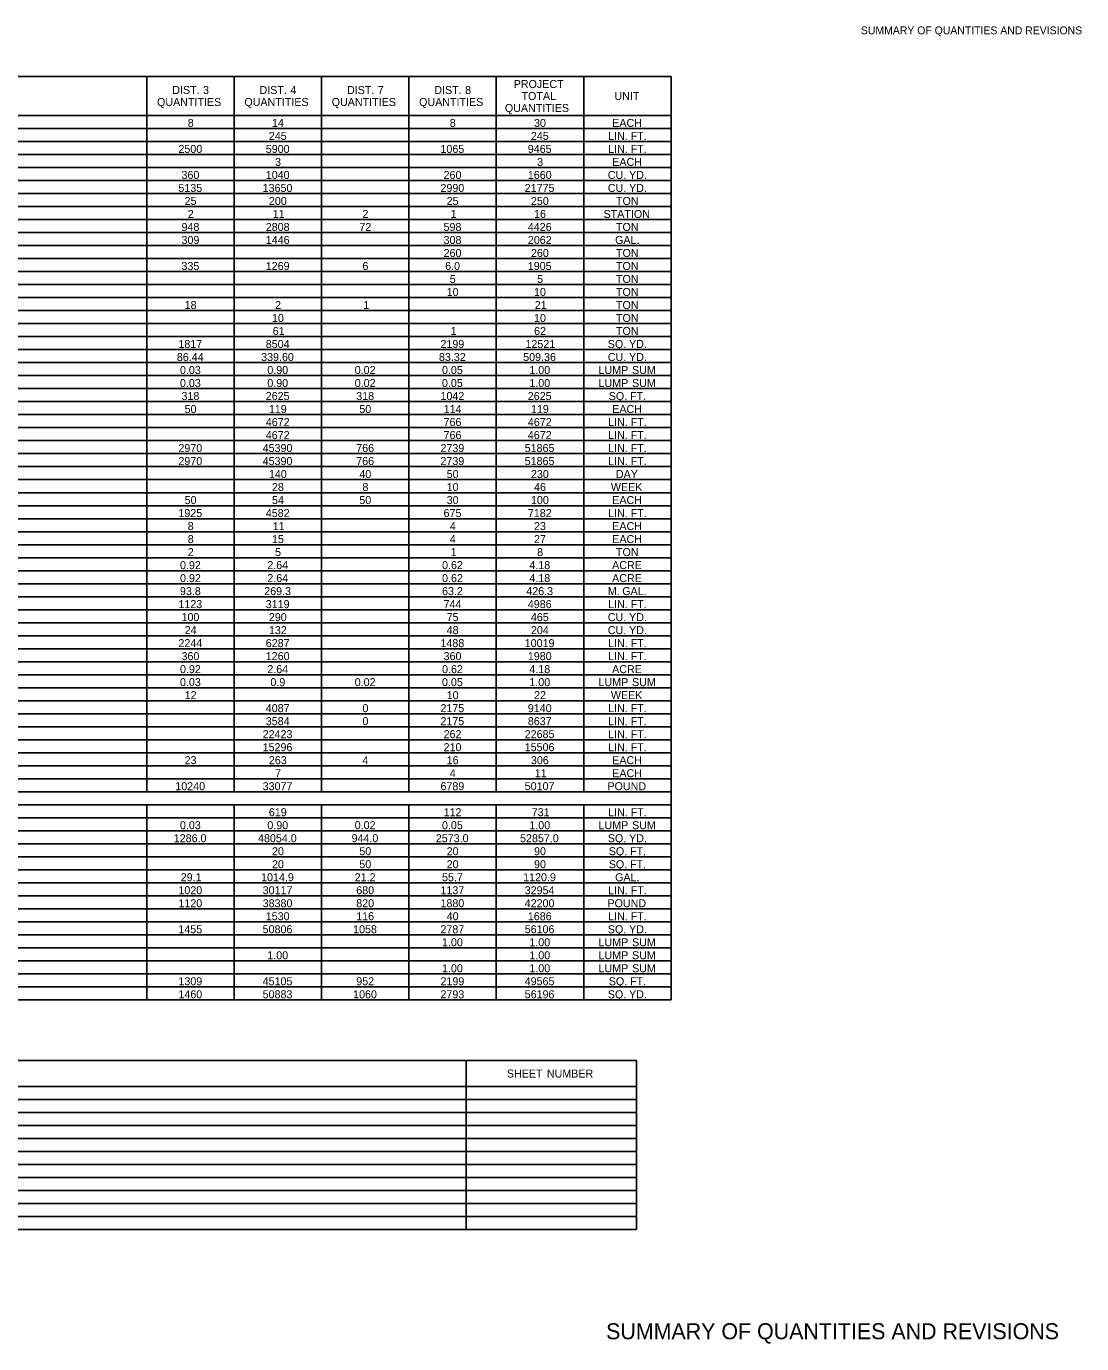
# Model space of a CAD drawing. Extents: x 540541 to 1930787, y -1948574 to 596640.
# Drawn here: x 548771 to 549562, y -1948574 to -1947586 of the extents above; entities that cross this region are included whole.
import ezdxf

# ---------------------------------------------------------------- set-up
doc = ezdxf.new("R2010")
doc.units = 0
for name, color, linetype in [('Default', 7, 'Continuous'), ('R_Border', 7, 'Continuous'), ('R_Border Prem', 7, 'Continuous')]:
    doc.layers.add(name, color=color, linetype=linetype)

msp = doc.modelspace()

# ---------------------------------------------------------------- linework, layer by layer
at = {"layer": 'Default'}
for p, q in [((548275.56, -1947623.57), (549254.46, -1947623.57)), ((548861.34, -1948159.82), (548861.34, -1947623.57)), ((548861.34, -1948042.82), (548861.34, -1947623.57)), ((548926.86, -1948159.82), (548926.86, -1947623.57)), ((548926.86, -1947652.82), (548926.86, -1947623.57)), ((548992.38, -1948159.82), (548992.38, -1947623.57)), ((548992.38, -1947652.82), (548992.38, -1947623.57)), ((549057.9, -1948159.82), (549057.9, -1947623.57)), ((549057.9, -1947652.82), (549057.9, -1947623.57)), ((549123.42, -1948159.82), (549123.42, -1947623.57)), ((549188.94, -1948159.82), (549188.94, -1947623.57)), ((549188.94, -1948159.82), (549188.94, -1947623.57)), ((549254.46, -1948315.82), (549254.46, -1947623.57)), ((548275.56, -1947652.82), (549254.46, -1947652.82)), ((548275.56, -1947652.82), (549254.46, -1947652.82)), ((548275.56, -1947662.57), (549254.46, -1947662.57)), ((548275.56, -1947672.32), (549254.46, -1947672.32)), ((548275.56, -1947682.07), (549254.46, -1947682.07)), ((548275.56, -1947691.82), (549254.46, -1947691.82)), ((548275.56, -1947701.57), (549254.46, -1947701.57)), ((548275.56, -1947711.32), (549254.46, -1947711.32)), ((548275.56, -1947721.07), (549254.46, -1947721.07)), ((548275.56, -1947730.82), (549254.46, -1947730.82)), ((548275.56, -1947740.57), (549254.46, -1947740.57)), ((548992.38, -1947750.32), (548992.38, -1947740.57)), ((549057.9, -1947750.32), (549057.9, -1947740.57)), ((548275.56, -1947750.32), (549254.46, -1947750.32)), ((548992.38, -1947750.32), (549057.9, -1947750.32)), ((549057.9, -1947750.32), (549254.46, -1947750.32)), ((548275.56, -1947760.07), (549254.46, -1947760.07)), ((548275.56, -1947769.82), (549254.46, -1947769.82)), ((548275.56, -1947779.57), (549254.46, -1947779.57)), ((548275.56, -1947789.32), (549254.46, -1947789.32)), ((548275.56, -1947799.07), (549254.46, -1947799.07)), ((548275.56, -1947808.82), (549254.46, -1947808.82)), ((548275.56, -1947818.57), (549254.46, -1947818.57)), ((548275.56, -1947828.32), (549254.46, -1947828.32)), ((548275.56, -1947838.07), (549254.46, -1947838.07)), ((548275.56, -1947847.82), (549254.46, -1947847.82)), ((548275.56, -1947857.57), (549254.46, -1947857.57)), ((548275.56, -1947867.32), (549254.46, -1947867.32)), ((548275.56, -1947877.07), (549254.46, -1947877.07)), ((548275.56, -1947886.82), (549254.46, -1947886.82)), ((548275.56, -1947896.57), (549254.46, -1947896.57)), ((548275.56, -1947906.32), (549254.46, -1947906.32)), ((548275.56, -1947916.07), (549254.46, -1947916.07)), ((548275.56, -1947925.82), (549254.46, -1947925.82)), ((548275.56, -1947935.57), (549254.46, -1947935.57)), ((548275.56, -1947945.32), (549254.46, -1947945.32)), ((548275.56, -1947955.07), (549254.46, -1947955.07)), ((548275.56, -1947964.82), (549254.46, -1947964.82)), ((548275.56, -1947974.57), (549254.46, -1947974.57)), ((548275.56, -1947984.32), (549254.46, -1947984.32)), ((548275.56, -1947994.07), (549254.46, -1947994.07)), ((548275.56, -1948003.82), (549254.46, -1948003.82)), ((548275.56, -1948013.57), (549254.46, -1948013.57)), ((548275.56, -1948023.32), (549254.46, -1948023.32)), ((548275.56, -1948033.07), (549254.46, -1948033.07)), ((548275.56, -1948042.82), (549254.46, -1948042.82)), ((548275.56, -1948052.57), (549254.46, -1948052.57)), ((548861.34, -1948159.82), (548861.34, -1948052.57)), ((549188.94, -1948052.57), (549254.46, -1948052.57)), ((548275.56, -1948062.32), (549254.46, -1948062.32)), ((548275.56, -1948072.07), (549254.46, -1948072.07)), ((548275.56, -1948081.82), (549254.46, -1948081.82)), ((548275.56, -1948091.57), (549254.46, -1948091.57)), ((548275.56, -1948101.32), (549254.46, -1948101.32)), ((548275.56, -1948111.07), (549254.46, -1948111.07)), ((548275.56, -1948120.82), (549254.46, -1948120.82)), ((548275.56, -1948130.57), (549254.46, -1948130.57)), ((548275.56, -1948140.32), (549254.46, -1948140.32)), ((548275.56, -1948150.07), (549254.46, -1948150.07)), ((548275.56, -1948159.82), (549254.46, -1948159.82)), ((548275.56, -1948159.82), (549254.46, -1948159.82)), ((548275.56, -1948169.57), (549254.46, -1948169.57)), ((548275.56, -1948169.57), (549254.46, -1948169.57)), ((548861.34, -1948179.32), (548861.34, -1948169.57)), ((548861.34, -1948315.82), (548861.34, -1948169.57)), ((548926.86, -1948315.82), (548926.86, -1948169.57)), ((548992.38, -1948315.82), (548992.38, -1948169.57)), ((549057.9, -1948315.82), (549057.9, -1948169.57)), ((549123.42, -1948315.82), (549123.42, -1948169.57)), ((549188.94, -1948315.82), (549188.94, -1948169.57)), ((549188.94, -1948315.82), (549188.94, -1948169.57)), ((548275.56, -1948179.32), (549254.46, -1948179.32)), ((549057.9, -1948189.07), (549057.9, -1948179.32)), ((549123.42, -1948189.07), (549123.42, -1948179.32)), ((548275.56, -1948189.07), (549254.46, -1948189.07)), ((548861.34, -1948315.82), (548861.34, -1948189.07)), ((548992.38, -1948198.82), (548992.38, -1948189.07)), ((548275.56, -1948198.82), (549254.46, -1948198.82)), ((548275.56, -1948208.57), (549254.46, -1948208.57)), ((548275.56, -1948218.32), (549254.46, -1948218.32)), ((548771.25, -1948218.32), (549123.42, -1948218.32)), ((549123.42, -1948218.32), (549254.46, -1948218.32)), ((548275.56, -1948228.07), (549254.46, -1948228.07)), ((548275.56, -1948237.82), (549254.46, -1948237.82)), ((548275.56, -1948247.57), (549254.46, -1948247.57)), ((548275.56, -1948257.32), (549254.46, -1948257.32)), ((548275.56, -1948267.07), (549254.46, -1948267.07)), ((548771.25, -1948267.07), (549123.42, -1948267.07)), ((549123.42, -1948267.07), (549254.46, -1948267.07)), ((548275.56, -1948276.82), (549254.46, -1948276.82)), ((548275.56, -1948286.57), (549254.46, -1948286.57)), ((548275.56, -1948296.32), (549254.46, -1948296.32)), ((548275.56, -1948306.07), (549254.46, -1948306.07)), ((548275.56, -1948315.82), (549254.46, -1948315.82)), ((548275.56, -1948361.31), (549228.62, -1948361.31)), ((549100.9, -1948361.31), (549228.62, -1948361.31)), ((549100.9, -1948380.81), (549100.9, -1948361.31)), ((549100.9, -1948488.06), (549100.9, -1948361.31)), ((549228.62, -1948488.06), (549228.62, -1948361.31)), ((549228.62, -1948488.06), (549228.62, -1948361.31)), ((548275.56, -1948380.81), (549228.62, -1948380.81)), ((548845.45, -1948380.81), (548909.31, -1948380.81)), ((549100.9, -1948380.81), (549228.62, -1948380.81)), ((548275.56, -1948390.56), (549228.62, -1948390.56)), ((548275.56, -1948400.31), (549228.62, -1948400.31)), ((548275.56, -1948410.06), (549228.62, -1948410.06)), ((548275.56, -1948419.81), (549228.62, -1948419.81)), ((548275.56, -1948429.56), (549228.62, -1948429.56)), ((548346.25, -1948429.56), (548845.45, -1948429.56)), ((548845.45, -1948429.56), (549228.62, -1948429.56)), ((548275.56, -1948439.31), (549228.62, -1948439.31)), ((548275.56, -1948449.06), (549228.62, -1948449.06)), ((548275.56, -1948458.81), (549228.62, -1948458.81)), ((548275.56, -1948468.56), (549228.62, -1948468.56)), ((548275.56, -1948478.31), (549228.62, -1948478.31)), ((548275.56, -1948488.06), (549228.62, -1948488.06))]:
    msp.add_line(p, q, dxfattribs=at)

# ---------------------------------------------------------------- texts
for s, p in [('PROJECT', (549136.47, -1947632.19)), ('DIST.', (548880.36, -1947636.69)), (' 3', (548901.21, -1947636.69)), ('DIST.', (548945.8, -1947636.69)), (' 4', (548966.65, -1947636.69)), ('DIST.', (549011.41, -1947636.69)), (' 7', (549032.26, -1947636.69)), ('DIST.', (549076.93, -1947636.69)), (' 8', (549097.78, -1947636.69)), ('TOTAL', (549142.33, -1947641.19)), ('UNIT', (549212.01, -1947641.19)), ('QUANTITIES', (548868.92, -1947645.69)), ('QUANTITIES', (548934.44, -1947645.69)), ('QUANTITIES', (548999.96, -1947645.69)), ('QUANTITIES', (549065.48, -1947645.69)), ('QUANTITIES', (549129.84, -1947650.19)), ('8', (548891.96, -1947661.37)), ('14', (548955.16, -1947661.37)), ('8', (549088.52, -1947661.37)), ('30', (549151.72, -1947661.37)), ('EACH', (549210.39, -1947661.37)), ('245', (548952.8, -1947671.12)), ('245', (549149.36, -1947671.12)), ('LIN.', (549207.3, -1947671.12)), (' FT.', (549221.94, -1947671.12)), ('2500', (548884.98, -1947680.87)), ('5900', (548950.5, -1947680.87)), ('1065', (549081.51, -1947680.87)), ('9465', (549147.03, -1947680.87)), ('LIN.', (549207.3, -1947680.87)), (' FT.', (549221.94, -1947680.87)), ('3', (548957.48, -1947690.62)), ('3', (549154.04, -1947690.62)), ('EACH', (549210.39, -1947690.62)), ('360', (548887.31, -1947700.37)), ('1040', (548950.5, -1947700.37)), ('260', (549083.87, -1947700.37)), ('1660', (549147.06, -1947700.37)), ('CU.', (549207.06, -1947700.37)), (' YD.', (549220.77, -1947700.37)), ('5135', (548884.95, -1947710.12)), ('13650', (548948.17, -1947710.12)), ('2990', (549081.54, -1947710.12)), ('21775', (549144.7, -1947710.12)), ('CU.', (549207.06, -1947710.12)), (' YD.', (549220.77, -1947710.12)), ('25', (548889.61, -1947719.87)), ('200', (548952.83, -1947719.87)), ('25', (549086.17, -1947719.87)), ('250', (549149.39, -1947719.87)), ('TON', (549213.19, -1947719.87)), ('2', (548891.99, -1947729.62)), ('11', (548955.73, -1947729.62)), ('2', (549023.03, -1947729.62)), ('1', (549089.1, -1947729.62)), ('16', (549151.71, -1947729.62)), ('STATION', (549203.88, -1947729.62)), ('948', (548887.3, -1947739.37)), ('2808', (548950.49, -1947739.37)), ('72', (549020.7, -1947739.37)), ('598', (549083.86, -1947739.37)), ('4426', (549147.05, -1947739.37)), ('TON', (549213.19, -1947739.37)), ('309', (548887.3, -1947749.12)), ('1446', (548950.49, -1947749.12)), ('308', (549083.86, -1947749.12)), ('2062', (549147.08, -1947749.12)), ('GAL.', (549212.52, -1947749.12)), ('260', (549083.87, -1947758.87)), ('260', (549149.39, -1947758.87)), ('TON', (549213.19, -1947758.87)), ('335', (548887.28, -1947768.62)), ('1269', (548950.49, -1947768.62)), ('6', (549023, -1947768.62)), ('6.0', (549085.04, -1947768.62)), ('1905', (549147.03, -1947768.62)), ('TON', (549213.19, -1947768.62)), ('5', (549088.5, -1947778.37)), ('5', (549154.02, -1947778.37)), ('TON', (549213.19, -1947778.37)), ('10', (549086.2, -1947788.12)), ('10', (549151.72, -1947788.12)), ('TON', (549213.19, -1947788.12)), ('18', (548889.63, -1947797.87)), ('2', (548957.51, -1947797.87)), ('1', (549023.58, -1947797.87)), ('21', (549152.29, -1947797.87)), ('TON', (549213.19, -1947797.87)), ('10', (548955.16, -1947807.62)), ('10', (549151.72, -1947807.62)), ('TON', (549213.19, -1947807.62)), ('61', (548955.73, -1947817.37)), ('1', (549089.1, -1947817.37)), ('62', (549151.74, -1947817.37)), ('TON', (549213.19, -1947817.37)), ('1817', (548884.97, -1947827.12)), ('8504', (548950.5, -1947827.12)), ('2199', (549081.53, -1947827.12)), ('12521', (549145.3, -1947827.12)), ('SQ.', (549207.06, -1947827.12)), (' YD.', (549220.77, -1947827.12)), ('86.44', (548883.82, -1947836.87)), ('339.60', (548947.01, -1947836.87)), ('83.32', (549080.4, -1947836.87)), ('509.36', (549143.56, -1947836.87)), ('CU.', (549207.06, -1947836.87)), (' YD.', (549220.77, -1947836.87)), ('0.03', (548886.14, -1947846.62)), ('0.90', (548951.67, -1947846.62)), ('0.02', (549017.21, -1947846.62)), ('0.05', (549082.67, -1947846.62)), ('1.00', (549148.23, -1947846.62)), ('LUMP', (549200.07, -1947846.62)), (' SUM', (549223, -1947846.62)), ('0.03', (548886.14, -1947856.37)), ('0.90', (548951.67, -1947856.37)), ('0.02', (549017.21, -1947856.37)), ('0.05', (549082.67, -1947856.37)), ('1.00', (549148.23, -1947856.37)), ('LUMP', (549200.07, -1947856.37)), (' SUM', (549223, -1947856.37)), ('318', (548887.3, -1947866.12)), ('2625', (548950.47, -1947866.12)), ('318', (549018.34, -1947866.12)), ('1042', (549081.56, -1947866.12)), ('2625', (549147.03, -1947866.12)), ('SQ.', (549207.76, -1947866.12)), (' FT.', (549221.47, -1947866.12)), ('50', (548889.64, -1947875.87)), ('119', (548952.82, -1947875.87)), ('50', (549020.68, -1947875.87)), ('114', (549083.87, -1947875.87)), ('119', (549149.38, -1947875.87)), ('EACH', (549210.39, -1947875.87)), ('4672', (548950.52, -1947885.62)), ('766', (549083.86, -1947885.62)), ('4672', (549147.08, -1947885.62)), ('LIN.', (549207.3, -1947885.62)), (' FT.', (549221.94, -1947885.62)), ('4672', (548950.52, -1947895.37)), ('766', (549083.86, -1947895.37)), ('4672', (549147.08, -1947895.37)), ('LIN.', (549207.3, -1947895.37)), (' FT.', (549221.94, -1947895.37)), ('2970', (548884.98, -1947905.12)), ('45390', (548948.17, -1947905.12)), ('766', (549018.34, -1947905.12)), ('2739', (549081.53, -1947905.12)), ('51865', (549144.7, -1947905.12)), ('LIN.', (549207.3, -1947905.12)), (' FT.', (549221.94, -1947905.12)), ('2970', (548884.98, -1947914.87)), ('45390', (548948.17, -1947914.87)), ('766', (549018.34, -1947914.87)), ('2739', (549081.53, -1947914.87)), ('51865', (549144.7, -1947914.87)), ('LIN.', (549207.3, -1947914.87)), (' FT.', (549221.94, -1947914.87)), ('140', (548952.83, -1947924.62)), ('40', (549020.68, -1947924.62)), ('50', (549086.2, -1947924.62)), ('230', (549149.39, -1947924.62)), ('DAY', (549213.11, -1947924.62)), ('28', (548955.15, -1947934.37)), ('8', (549023, -1947934.37)), ('10', (549086.2, -1947934.37)), ('46', (549151.71, -1947934.37)), ('WEEK', (549209.36, -1947934.37)), ('50', (548889.64, -1947944.12)), ('54', (548955.16, -1947944.12)), ('50', (549020.68, -1947944.12)), ('30', (549086.2, -1947944.12)), ('100', (549149.39, -1947944.12)), ('EACH', (549210.39, -1947944.12)), ('1925', (548884.95, -1947953.87)), ('4582', (548950.52, -1947953.87)), ('675', (549083.84, -1947953.87)), ('7182', (549147.08, -1947953.87)), ('LIN.', (549207.3, -1947953.87)), (' FT.', (549221.94, -1947953.87)), ('8', (548891.96, -1947963.62)), ('11', (548955.73, -1947963.62)), ('4', (549088.53, -1947963.62)), ('23', (549151.71, -1947963.62)), ('EACH', (549210.39, -1947963.62)), ('8', (548891.96, -1947973.37)), ('15', (548955.13, -1947973.37)), ('4', (549088.53, -1947973.37)), ('27', (549151.71, -1947973.37)), ('EACH', (549210.39, -1947973.37)), ('2', (548891.99, -1947983.12)), ('5', (548957.46, -1947983.12)), ('1', (549089.1, -1947983.12)), ('8', (549154.04, -1947983.12)), ('TON', (549213.19, -1947983.12)), ('0.92', (548886.17, -1947992.87)), ('2.64', (548951.67, -1947992.87)), ('0.62', (549082.73, -1947992.87)), ('4.18', (549148.21, -1947992.87)), ('ACRE', (549210.28, -1947992.87)), ('0.92', (548886.17, -1948002.62)), ('2.64', (548951.67, -1948002.62)), ('0.62', (549082.73, -1948002.62)), ('4.18', (549148.21, -1948002.62)), ('ACRE', (549210.28, -1948002.62)), ('93.8', (548886.13, -1948012.37)), ('269.3', (548949.33, -1948012.37)), ('63.2', (549082.73, -1948012.37)), ('426.3', (549145.89, -1948012.37)), ('M.', (549207.06, -1948012.37)), (' GAL.', (549215.64, -1948012.37)), ('1123', (548884.97, -1948022.12)), ('3119', (548950.49, -1948022.12)), ('744', (549083.87, -1948022.12)), ('4986', (549147.05, -1948022.12)), ('LIN.', (549207.3, -1948022.12)), (' FT.', (549221.94, -1948022.12)), ('100', (548887.31, -1948031.87)), ('290', (548952.83, -1948031.87)), ('75', (549086.17, -1948031.87)), ('465', (549149.36, -1948031.87)), ('CU.', (549207.06, -1948031.87)), (' YD.', (549220.77, -1948031.87)), ('24', (548889.64, -1948041.62)), ('132', (548952.85, -1948041.62)), ('48', (549086.19, -1948041.62)), ('204', (549149.39, -1948041.62)), ('CU.', (549207.06, -1948041.62)), (' YD.', (549220.77, -1948041.62)), ('2244', (548884.98, -1948051.37)), ('6287', (548950.49, -1948051.37)), ('1488', (549081.53, -1948051.37)), ('10019', (549144.72, -1948051.37)), ('LIN.', (549207.3, -1948051.37)), (' FT.', (549221.94, -1948051.37)), ('360', (548887.31, -1948061.12)), ('1260', (548950.5, -1948061.12)), ('360', (549083.87, -1948061.12)), ('1980', (549147.06, -1948061.12)), ('LIN.', (549207.3, -1948061.12)), (' FT.', (549221.94, -1948061.12)), ('0.92', (548886.17, -1948070.87)), ('2.64', (548951.67, -1948070.87)), ('0.62', (549082.73, -1948070.87)), ('4.18', (549148.21, -1948070.87)), ('ACRE', (549210.28, -1948070.87)), ('0.03', (548886.14, -1948080.62)), ('0.9', (548953.98, -1948080.62)), ('0.02', (549017.21, -1948080.62)), ('0.05', (549082.67, -1948080.62)), ('1.00', (549148.23, -1948080.62)), ('LUMP', (549200.07, -1948080.62)), (' SUM', (549223, -1948080.62)), ('12', (548889.66, -1948090.37)), ('10', (549086.2, -1948090.37)), ('22', (549151.74, -1948090.37)), ('WEEK', (549209.36, -1948090.37)), ('4087', (548950.49, -1948100.12)), ('0', (549023.01, -1948100.12)), ('2175', (549081.51, -1948100.12)), ('9140', (549147.06, -1948100.12)), ('LIN.', (549207.3, -1948100.12)), (' FT.', (549221.94, -1948100.12)), ('3584', (548950.5, -1948109.87)), ('0', (549023.01, -1948109.87)), ('2175', (549081.51, -1948109.87)), ('8637', (549147.05, -1948109.87)), ('LIN.', (549207.3, -1948109.87)), (' FT.', (549221.94, -1948109.87)), ('22423', (548948.16, -1948119.62)), ('262', (549083.89, -1948119.62)), ('22685', (549144.7, -1948119.62)), ('LIN.', (549207.3, -1948119.62)), (' FT.', (549221.94, -1948119.62)), ('15296', (548948.16, -1948129.37)), ('210', (549083.87, -1948129.37)), ('15506', (549144.72, -1948129.37)), ('LIN.', (549207.3, -1948129.37)), (' FT.', (549221.94, -1948129.37)), ('23', (548889.63, -1948139.12)), ('263', (548952.82, -1948139.12)), ('4', (549023.01, -1948139.12)), ('16', (549086.19, -1948139.12)), ('306', (549149.38, -1948139.12)), ('EACH', (549210.39, -1948139.12)), ('7', (548957.48, -1948148.87)), ('4', (549088.53, -1948148.87)), ('11', (549152.29, -1948148.87)), ('EACH', (549210.39, -1948148.87)), ('10240', (548882.65, -1948158.62)), ('33077', (548948.16, -1948158.62)), ('6789', (549081.53, -1948158.62)), ('50107', (549144.72, -1948158.62)), ('POUND', (549206.78, -1948158.62)), ('619', (548952.82, -1948178.12)), ('112', (549083.89, -1948178.12)), ('731', (549149.96, -1948178.12)), ('LIN.', (549207.3, -1948178.12)), (' FT.', (549221.94, -1948178.12)), ('0.03', (548886.14, -1948187.87)), ('0.90', (548951.67, -1948187.87)), ('0.02', (549017.21, -1948187.87)), ('0.05', (549082.67, -1948187.87)), ('1.00', (549148.23, -1948187.87)), ('LUMP', (549200.07, -1948187.87)), (' SUM', (549223, -1948187.87)), ('1286.0', (548881.49, -1948197.62)), ('48054.0', (548944.68, -1948197.62)), ('944.0', (549014.86, -1948197.62)), ('2573.0', (549078.05, -1948197.62)), ('52857.0', (549141.24, -1948197.62)), ('SQ.', (549207.06, -1948197.62)), (' YD.', (549220.77, -1948197.62)), ('20', (548955.16, -1948207.37)), ('50', (549020.68, -1948207.37)), ('20', (549086.2, -1948207.37)), ('90', (549151.72, -1948207.37)), ('SQ.', (549207.76, -1948207.37)), (' FT.', (549221.47, -1948207.37)), ('20', (548955.16, -1948217.12)), ('50', (549020.68, -1948217.12)), ('20', (549086.2, -1948217.12)), ('90', (549151.72, -1948217.12)), ('SQ.', (549207.76, -1948217.12)), (' FT.', (549221.47, -1948217.12)), ('29.1', (548886.72, -1948226.87)), ('1014.9', (548946.99, -1948226.87)), ('21.2', (549017.21, -1948226.87)), ('55.7', (549082.7, -1948226.87)), ('1120.9', (549143.55, -1948226.87)), ('GAL.', (549212.52, -1948226.87)), ('1020', (548884.98, -1948236.62)), ('30117', (548948.16, -1948236.62)), ('680', (549018.35, -1948236.62)), ('1137', (549081.53, -1948236.62)), ('32954', (549144.73, -1948236.62)), ('LIN.', (549207.3, -1948236.62)), (' FT.', (549221.94, -1948236.62)), ('1120', (548884.98, -1948246.37)), ('38380', (548948.17, -1948246.37)), ('820', (549018.35, -1948246.37)), ('1880', (549081.54, -1948246.37)), ('42200', (549144.73, -1948246.37)), ('POUND', (549206.78, -1948246.37)), ('1530', (548950.5, -1948256.12)), ('116', (549018.34, -1948256.12)), ('40', (549086.2, -1948256.12)), ('1686', (549147.05, -1948256.12)), ('LIN.', (549207.3, -1948256.12)), (' FT.', (549221.94, -1948256.12)), ('1455', (548884.95, -1948265.87)), ('50806', (548948.16, -1948265.87)), ('1058', (549016.01, -1948265.87)), ('2787', (549081.53, -1948265.87)), ('56106', (549144.72, -1948265.87)), ('SQ.', (549207.06, -1948265.87)), (' YD.', (549220.77, -1948265.87)), ('1.00', (549082.71, -1948275.62)), ('1.00', (549148.23, -1948275.62)), ('LUMP', (549200.07, -1948275.62)), (' SUM', (549223, -1948275.62)), ('1.00', (548951.67, -1948285.37)), ('1.00', (549148.23, -1948285.37)), ('LUMP', (549200.07, -1948285.37)), (' SUM', (549223, -1948285.37)), ('1.00', (549082.71, -1948295.12)), ('1.00', (549148.23, -1948295.12)), ('LUMP', (549200.07, -1948295.12)), (' SUM', (549223, -1948295.12)), ('1309', (548884.97, -1948304.87)), ('45105', (548948.14, -1948304.87)), ('952', (549018.37, -1948304.87)), ('2199', (549081.53, -1948304.87)), ('49565', (549144.7, -1948304.87)), ('SQ.', (549207.76, -1948304.87)), (' FT.', (549221.47, -1948304.87)), ('1460', (548884.98, -1948314.62)), ('50883', (548948.16, -1948314.62)), ('1060', (549016.02, -1948314.62)), ('2793', (549081.53, -1948314.62)), ('56196', (549144.72, -1948314.62)), ('SQ.', (549207.06, -1948314.62)), (' YD.', (549220.77, -1948314.62)), ('SHEET', (549131.33, -1948374.06)), (' NUMBER', (549159.11, -1948374.06))]:
    msp.add_text(s, height=6, dxfattribs=at).set_placement(p)
at = {"layer": 'R_Border'}
msp.add_text('SUMMARY OF QUANTITIES AND REVISIONS', height=12, rotation=360, dxfattribs=at).set_placement((549205.77, -1948570.24))
at = {"layer": 'R_Border Prem'}
msp.add_text('SUMMARY OF QUANTITIES AND REVISIONS', height=5.862, rotation=360, dxfattribs=at).set_placement((549396.9, -1947591.92))

doc.saveas('drawing.dxf')
